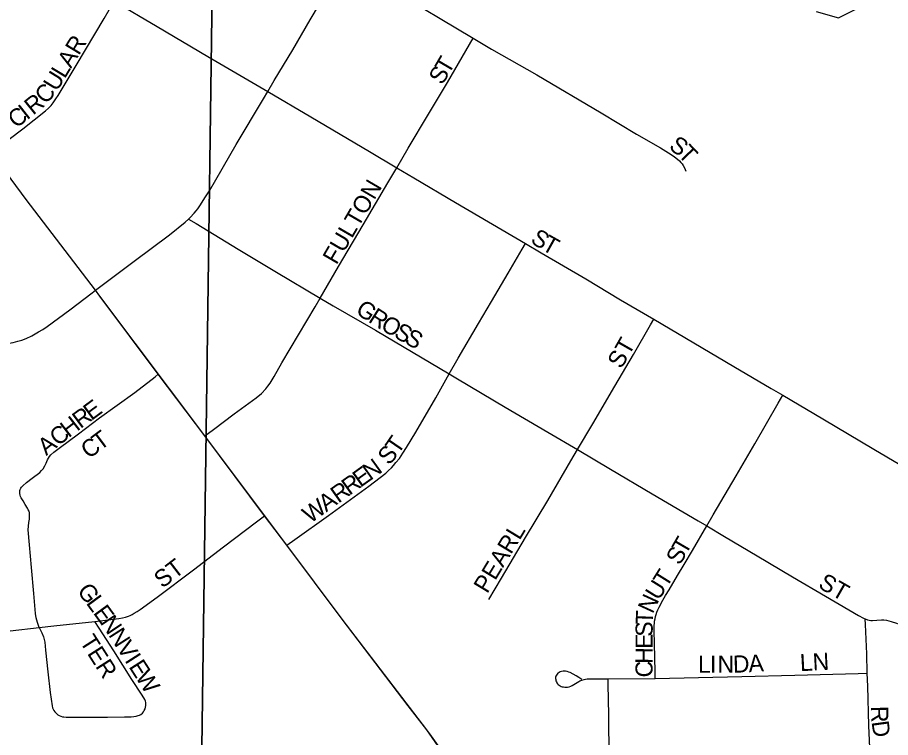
# Model space of a CAD drawing. Extents: x 0 to 34, y 0 to 22.
# Drawn here: x 5.9357 to 6.1771, y 18.1386 to 18.3375 of the extents above; entities that cross this region are included whole.
import ezdxf

# ---------------------------------------------------------------- set-up
doc = ezdxf.new("R2010")
doc.units = 0
for name, color, linetype in [('Default', 7, 'Continuous'), ('GM_X_City_Street', 7, 'Continuous'), ('GM_X_City_Street_Text', 7, 'Continuous'), ('GM_X_Minor_River', 7, 'Continuous'), ('GM_X_Section', 7, 'Continuous'), ('GM_X_State_Route', 7, 'Continuous')]:
    doc.layers.add(name, color=color, linetype=linetype)

msp = doc.modelspace()

# ---------------------------------------------------------------- linework, layer by layer
at = {"layer": 'Default'}
msp.add_lwpolyline([(6.21175, 17.82109), (6.19182, 17.86034), (6.14526, 17.95216), (6.11969, 18.00306), (6.11076, 18.02099), (6.07084, 18.10026), (6.06147, 18.11896), (6.05496, 18.13197), (6.04884, 18.14072), (6.02545, 18.17135), (6.01014, 18.19175), (5.98748, 18.22193), (5.95849, 18.26057), (5.9573, 18.26217)], dxfattribs=at)
at = {"layer": 'GM_X_City_Street'}
for points in [[(6.00491, 18.31708), (6.0067, 18.32012), (6.01183, 18.32859), (6.01666, 18.33686), (6.0261, 18.35291)], [(6.0261, 18.35291), (6.02799, 18.35183), (6.03473, 18.34796), (6.04394, 18.34247), (6.05254, 18.33728), (6.06168, 18.33184)], [(5.92844, 18.30025), (5.93343, 18.30396), (5.93716, 18.30674), (5.9435, 18.31176), (5.94429, 18.31246), (5.94502, 18.31325), (5.94559, 18.31399), (5.94634, 18.31505), (5.94696, 18.31599), (5.95193, 18.32428), (5.9597, 18.33726), (5.96247, 18.34205)], [(5.96247, 18.34205), (5.97435, 18.33504), (5.98831, 18.32678), (6.00491, 18.31708)], [(6.04056, 18.29602), (6.04373, 18.3014), (6.04931, 18.31082), (6.0546, 18.31959), (6.06168, 18.33184)], [(6.06168, 18.33184), (6.06679, 18.32881), (6.07927, 18.32166), (6.09708, 18.31118), (6.10683, 18.30534), (6.11345, 18.30152), (6.11637, 18.29971), (6.11729, 18.29908), (6.11813, 18.29844), (6.11868, 18.29794), (6.11909, 18.29751), (6.11942, 18.29708), (6.11971, 18.29669), (6.1201, 18.29601), (6.12048, 18.29511)], [(5.983, 18.28182), (5.98349, 18.28232), (5.98458, 18.28348), (5.98508, 18.28412), (5.98553, 18.28471), (5.98635, 18.28582), (5.98754, 18.28767), (5.98882, 18.28969), (5.99619, 18.30243), (6.00369, 18.31502), (6.00491, 18.31708)], [(6.00491, 18.31708), (6.01677, 18.31005), (6.03302, 18.30051), (6.04056, 18.29602)], [(6.01939, 18.26003), (6.02448, 18.26873), (6.0313, 18.28029), (6.03812, 18.29189), (6.04056, 18.29602)], [(6.04056, 18.29602), (6.04532, 18.2932), (6.05679, 18.28646), (6.07614, 18.27507)], [(5.9573, 18.26217), (5.96797, 18.27019), (5.97772, 18.27747), (5.98211, 18.28101), (5.983, 18.28182)], [(5.983, 18.28182), (5.98507, 18.28058), (5.9967, 18.27355), (6.00734, 18.26722), (6.01939, 18.26003)], [(6.05503, 18.23906), (6.05751, 18.24346), (6.06318, 18.25296), (6.06676, 18.25909), (6.07132, 18.26686), (6.07523, 18.27352), (6.07614, 18.27507)], [(6.07614, 18.27507), (6.08052, 18.2725), (6.09282, 18.26529), (6.1024, 18.25957), (6.11158, 18.25418)], [(5.92009, 18.24581), (5.92855, 18.24682), (5.93286, 18.24744), (5.93451, 18.24777), (5.93582, 18.2481), (5.93693, 18.24843), (5.93808, 18.24888), (5.93965, 18.24962), (5.94154, 18.25065), (5.94269, 18.25135), (5.94396, 18.25217), (5.95018, 18.25674), (5.95633, 18.26143), (5.9573, 18.26217)], [(5.98748, 18.22193), (5.98991, 18.22374), (5.99566, 18.22802), (6.00167, 18.23244), (6.00314, 18.23369), (6.00438, 18.23498), (6.00495, 18.23571), (6.00557, 18.23653), (6.00664, 18.23834), (6.00877, 18.24212), (6.01798, 18.25763), (6.01939, 18.26003)], [(6.01939, 18.26003), (6.02298, 18.25789), (6.03466, 18.25119), (6.05503, 18.23906)], [(6.09054, 18.21815), (6.09477, 18.22523), (6.10085, 18.23567), (6.10599, 18.24447), (6.11068, 18.25262), (6.11158, 18.25418)], [(6.11158, 18.25418), (6.13374, 18.24108), (6.14402, 18.23508), (6.1473, 18.23315)], [(5.94169, 18.16903), (5.94127, 18.17036), (5.94107, 18.17101), (5.9409, 18.17167), (5.94074, 18.17286), (5.94028, 18.17841), (5.93958, 18.18557), (5.93905, 18.19186), (5.93871, 18.19601), (5.93876, 18.197), (5.93888, 18.19803), (5.93902, 18.19893), (5.93908, 18.19959), (5.93908, 18.20017), (5.93904, 18.2007), (5.93891, 18.20115), (5.93872, 18.20154), (5.93847, 18.20197), (5.93789, 18.20296), (5.93728, 18.20399), (5.93678, 18.20481), (5.93659, 18.20522), (5.93644, 18.20559), (5.93636, 18.20604), (5.93633, 18.20646), (5.9364, 18.20687), (5.9365, 18.20713), (5.93667, 18.20749), (5.93687, 18.20775), (5.93719, 18.20814), (5.93822, 18.20909), (5.93974, 18.21028), (5.94186, 18.2118), (5.94239, 18.21234), (5.9428, 18.21287), (5.94325, 18.21365), (5.94362, 18.21439), (5.94404, 18.2153), (5.94432, 18.21583), (5.94461, 18.21624), (5.94498, 18.2167), (5.9458, 18.21744), (5.94728, 18.21859), (5.95255, 18.2225), (5.95839, 18.2269), (5.96817, 18.23397), (5.97376, 18.23829), (5.97463, 18.23897)], [(6.01014, 18.19175), (6.01242, 18.19336), (6.02167, 18.19994), (6.03281, 18.20805), (6.0375, 18.21167), (6.03832, 18.21237), (6.03912, 18.21315), (6.03967, 18.21372), (6.04033, 18.21455), (6.04128, 18.21574), (6.04226, 18.21714), (6.04321, 18.2187), (6.04584, 18.22294), (6.05134, 18.2325), (6.05503, 18.23906)], [(6.05503, 18.23906), (6.05736, 18.23767), (6.07057, 18.2299), (6.08233, 18.22299), (6.09054, 18.21815)], [(6.12624, 18.19706), (6.12801, 18.2001), (6.13434, 18.21095), (6.13952, 18.21979), (6.14602, 18.23094), (6.1473, 18.23315)], [(6.1473, 18.23315), (6.15835, 18.22666), (6.17244, 18.21827), (6.1796, 18.21401)], [(6.06604, 18.17674), (6.06953, 18.18262), (6.07619, 18.19389), (6.08232, 18.20413), (6.08869, 18.21507), (6.09054, 18.21815)], [(6.09054, 18.21815), (6.09968, 18.21276), (6.11112, 18.20593), (6.12391, 18.19846), (6.12624, 18.19706)], [(5.95713, 18.17067), (5.96374, 18.17145), (5.96479, 18.17166), (5.96557, 18.17187), (5.96637, 18.17214), (5.96691, 18.17234), (5.96738, 18.17257), (5.968, 18.17292), (5.96884, 18.17345), (5.9696, 18.17398), (5.97437, 18.1774), (5.98436, 18.18494), (5.99266, 18.19125), (6.00178, 18.19821), (6.004, 18.1999)], [(6.11203, 18.15495), (6.11199, 18.15675), (6.11178, 18.1646), (6.1117, 18.1681), (6.11174, 18.16954), (6.11177, 18.1702), (6.11185, 18.17079), (6.11197, 18.17143), (6.11211, 18.17205), (6.11228, 18.17264), (6.11248, 18.1732), (6.11277, 18.1739), (6.11313, 18.17464), (6.11414, 18.17653), (6.11485, 18.17781), (6.11584, 18.17945), (6.11815, 18.18336), (6.11996, 18.18638), (6.1223, 18.19031), (6.12624, 18.19706)], [(6.12624, 18.19706), (6.13114, 18.19414), (6.14019, 18.18884), (6.14998, 18.18304), (6.15911, 18.1777), (6.16553, 18.17392), (6.1682, 18.17236), (6.1696, 18.17162), (6.17003, 18.17141)], [(5.94169, 18.16903), (5.94242, 18.16753), (5.94291, 18.16647), (5.94304, 18.16606), (5.94314, 18.16573), (5.9432, 18.16533), (5.94326, 18.16496), (5.94346, 18.16278), (5.94408, 18.15674), (5.94476, 18.15107), (5.94528, 18.14732), (5.94542, 18.14683), (5.94557, 18.14644), (5.9458, 18.14605), (5.94605, 18.14568), (5.94629, 18.14539), (5.94658, 18.14512), (5.94687, 18.1449), (5.94728, 18.14467), (5.94769, 18.14449), (5.94814, 18.14437), (5.94851, 18.1443), (5.94919, 18.14424), (5.94996, 18.14424), (5.95428, 18.14424), (5.96062, 18.14424), (5.9653, 18.14429), (5.96714, 18.14434), (5.9679, 18.14441), (5.96856, 18.14452), (5.96909, 18.14466), (5.96947, 18.14478), (5.96985, 18.14501), (5.97025, 18.14534), (5.97051, 18.14567), (5.97078, 18.14606), (5.97098, 18.14651), (5.97115, 18.147), (5.97121, 18.14741), (5.97122, 18.14774), (5.97119, 18.14826), (5.97109, 18.14867), (5.97092, 18.14908), (5.97015, 18.15029), (5.96737, 18.15463), (5.96234, 18.16254), (5.95831, 18.16883), (5.95713, 18.17067)], [(5.94169, 18.16903), (5.94575, 18.16948), (5.95713, 18.17067)], [(6.17063, 18.15636), (6.17048, 18.16172), (6.17011, 18.16986), (6.17003, 18.17141)], [(6.17003, 18.17141), (6.17072, 18.17112), (6.17111, 18.171), (6.17156, 18.17094), (6.17202, 18.17092), (6.17326, 18.171), (6.17457, 18.17108), (6.1752, 18.17108), (6.17589, 18.171), (6.17658, 18.17086), (6.17721, 18.17067), (6.17872, 18.17018), (6.17958, 18.16985), (6.1804, 18.16948), (6.18127, 18.16907), (6.18222, 18.16858), (6.18827, 18.16512), (6.19596, 18.16052), (6.20472, 18.15509), (6.20982, 18.15185)], [(5.93371, 18.16813), (5.94169, 18.16903)], [(6.09174, 18.15461), (6.09085, 18.15518), (6.09014, 18.15561), (6.08847, 18.15656), (6.08813, 18.1567), (6.0877, 18.15686), (6.08725, 18.15695), (6.0869, 18.15696), (6.08657, 18.15695), (6.08613, 18.15686), (6.08576, 18.15674), (6.08544, 18.15659), (6.08511, 18.15637), (6.08486, 18.15612), (6.08468, 18.15586), (6.08455, 18.15557), (6.08447, 18.15526), (6.08445, 18.15491), (6.08449, 18.1546), (6.08457, 18.15425), (6.08468, 18.15399), (6.0848, 18.15372), (6.08497, 18.15347), (6.08519, 18.15322), (6.08542, 18.15304), (6.08571, 18.15287), (6.08599, 18.15275), (6.0863, 18.15265), (6.08665, 18.15257), (6.08698, 18.15252), (6.08741, 18.15248), (6.0878, 18.15252), (6.08821, 18.15263), (6.08867, 18.15281), (6.08905, 18.15302), (6.08954, 18.15329), (6.09046, 18.15383), (6.09085, 18.15405), (6.0912, 18.15424), (6.09145, 18.15434), (6.09176, 18.15446), (6.09238, 18.15465), (6.09276, 18.15473), (6.0932, 18.15479), (6.09385, 18.15481), (6.09519, 18.15483), (6.09901, 18.15481)], [(6.11203, 18.15495), (6.1359, 18.15546), (6.15058, 18.15583), (6.16812, 18.15629), (6.17063, 18.15636)], [(6.17167, 18.12678), (6.17156, 18.12969), (6.17107, 18.14192), (6.17077, 18.15276), (6.17063, 18.15636)], [(6.09901, 18.15481), (6.11203, 18.15495)], [(6.09931, 18.13309), (6.09915, 18.14479), (6.09903, 18.15334), (6.09901, 18.15481)]]:
    msp.add_lwpolyline(points, dxfattribs=at)
at = {"layer": 'GM_X_Minor_River'}
msp.add_lwpolyline([(6.15646, 18.33923), (6.16271, 18.33747), (6.16804, 18.34009)], dxfattribs=at)
at = {"layer": 'GM_X_Section'}
for points in [[(5.99052, 18.41894), (5.98372, 17.92012), (5.4644, 17.92291), (5.46396, 18.4161)], [(6.50305, 18.41943), (6.4928, 17.91626), (5.98372, 17.92012), (5.99052, 18.41894)]]:
    msp.add_lwpolyline(points, close=True, dxfattribs=at)
at = {"layer": 'GM_X_State_Route'}
for points in [[(5.95849, 18.26057), (5.9573, 18.26217), (5.93814, 18.28724), (5.92844, 18.30025), (5.92011, 18.31141), (5.90665, 18.32923), (5.90056, 18.33741), (5.88686, 18.35577), (5.88585, 18.35712), (5.86684, 18.38286), (5.85489, 18.39869), (5.85329, 18.40095), (5.84979, 18.40613), (5.84897, 18.40736), (5.84819, 18.40843), (5.84757, 18.40917), (5.847, 18.40979), (5.84691, 18.40987), (5.8452, 18.41119), (5.84367, 18.41232), (5.84214, 18.41341), (5.84042, 18.41464), (5.83893, 18.41568), (5.83726, 18.41681)], [(6.0975, 18.04739), (6.09569, 18.05096), (6.09058, 18.06106), (6.08127, 18.07964), (6.07084, 18.10026), (6.0668, 18.10829), (6.06147, 18.11896), (6.05756, 18.12698), (6.05649, 18.12916), (6.0554, 18.13118), (6.05443, 18.13286), (6.0537, 18.13397), (6.05197, 18.13644), (6.05016, 18.13895), (6.04884, 18.14072), (6.04367, 18.14733), (6.02545, 18.17135), (6.01014, 18.19175), (6.004, 18.1999), (5.98748, 18.22193), (5.97463, 18.23897), (5.95849, 18.26057)]]:
    msp.add_lwpolyline(points, dxfattribs=at)

# ---------------------------------------------------------------- texts
at = {"layer": 'GM_X_City_Street_Text'}
for s, height, rotation, p in [('R', 0.00473, 58.803, (5.95267, 18.32687)), ('A', 0.00473, 58.8169, (5.95051, 18.3233)), ('T', 0.00473, 59.5818, (6.0549, 18.32159)), ('U', 0.00473, 58.3728, (5.94658, 18.31687)), ('L', 0.00473, 58.7903, (5.94878, 18.32045)), ('S', 0.00473, 58.4319, (6.05311, 18.31866)), ('C', 0.00473, 48.498, (5.94356, 18.31335)), ('R', 0.00473, 38.8917, (5.94002, 18.3104)), ('C', 0.00473, 38.0454, (5.93536, 18.30675)), ('I', 0.00473, 38.0483, (5.93832, 18.30906)), ('S', 0.00473, 323.7858, (6.11552, 18.3014)), ('T', 0.00473, 313.6669, (6.11805, 18.29958)), ('FULTON', 0.004735, 59.7419, (6.02389, 18.269)), ('S', 0.00473, 327.0826, (6.07725, 18.27553)), ('T', 0.00473, 330.8247, (6.08034, 18.27354)), ('G', 0.00473, 326.419, (6.0289, 18.25595)), ('R', 0.00473, 327.4493, (6.03245, 18.2536)), ('O', 0.00473, 330.293, (6.03583, 18.25145)), ('S', 0.00473, 330.7518, (6.03949, 18.24936)), ('S', 0.00473, 330.7464, (6.0424, 18.24773)), ('ST', 0.004735, 60.2568, (6.10264, 18.24024)), ('E', 0.00473, 36.389, (5.95614, 18.22603)), ('R', 0.00473, 36.4862, (5.95312, 18.2238)), ('H', 0.00473, 37.8577, (5.94986, 18.22126)), ('C', 0.00473, 38.6333, (5.94694, 18.21893)), ('T', 0.00473, 36.7849, (5.95853, 18.2177)), ('A', 0.00473, 38.6359, (5.94368, 18.21633)), ('C', 0.00473, 35.5828, (5.95539, 18.21545)), ('T', 0.00473, 55.5761, (6.04096, 18.2166)), ('S', 0.00473, 49.1941, (6.03843, 18.21362)), ('E', 0.00473, 35.6557, (6.03053, 18.20757)), ('N', 0.00473, 35.7908, (6.03325, 18.20952)), ('R', 0.00473, 35.6506, (6.02443, 18.2032)), ('R', 0.00473, 35.6506, (6.02748, 18.20538)), ('W', 0.00473, 35.6491, (6.01665, 18.19761)), ('A', 0.00473, 35.6546, (6.02105, 18.20077)), ('PEARL', 0.004735, 58.8135, (6.06556, 18.17817)), ('T', 0.00473, 59.8281, (6.12045, 18.18887)), ('S', 0.00473, 60.7464, (6.11883, 18.18598)), ('ST', 0.004735, 37.5629, (5.97578, 18.17967)), ('T', 0.00473, 57.9772, (6.11516, 18.17979)), ('U', 0.00473, 58.2564, (6.11298, 18.17625)), ('ST', 0.004735, 330.2568, (6.15677, 18.18015)), ('G', 0.00473, 306.4371, (5.95204, 18.17908)), ('L', 0.00473, 306.411, (5.95452, 18.17572)), ('N', 0.00473, 65.3119, (6.11131, 18.1726)), ('E', 0.00473, 306.2142, (5.95649, 18.17304)), ('N', 0.00473, 303.8658, (5.95843, 18.1704)), ('T', 0.00473, 88.0053, (6.11131, 18.16975)), ('S', 0.00473, 89.8324, (6.1113, 18.16646)), ('N', 0.00473, 302.617, (5.96074, 18.16696)), ('TER', 0.004735, 302.4718, (5.95278, 18.16512)), ('V', 0.00473, 302.5383, (5.96298, 18.16345)), ('E', 0.00473, 89.8324, (6.11129, 18.16312)), ('H', 0.00473, 89.8353, (6.11128, 18.15896)), ('I', 0.00473, 302.5383, (5.96523, 18.15994)), ('L', 0.00473, 0.0546, (6.12383, 18.1565)), ('I', 0.00473, 0.0437, (6.12716, 18.15651)), ('N', 0.00473, 0.0379, (6.12924, 18.15651)), ('D', 0.00473, 1.6498, (6.13355, 18.15651)), ('A', 0.00473, 3.7722, (6.13791, 18.15664)), ('LN', 0.004735, 3.011, (6.15211, 18.15692)), ('E', 0.00473, 302.5722, (5.96635, 18.15818)), ('C', 0.00473, 89.83, (6.11127, 18.15521)), ('W', 0.00473, 302.5383, (5.96814, 18.15537)), ('R', 0.00473, 271.3599, (6.17166, 18.14727)), ('D', 0.00473, 277.756, (6.17179, 18.14295))]:
    msp.add_text(s, height=height, rotation=rotation, dxfattribs=at).set_placement(p)

doc.saveas('drawing.dxf')
